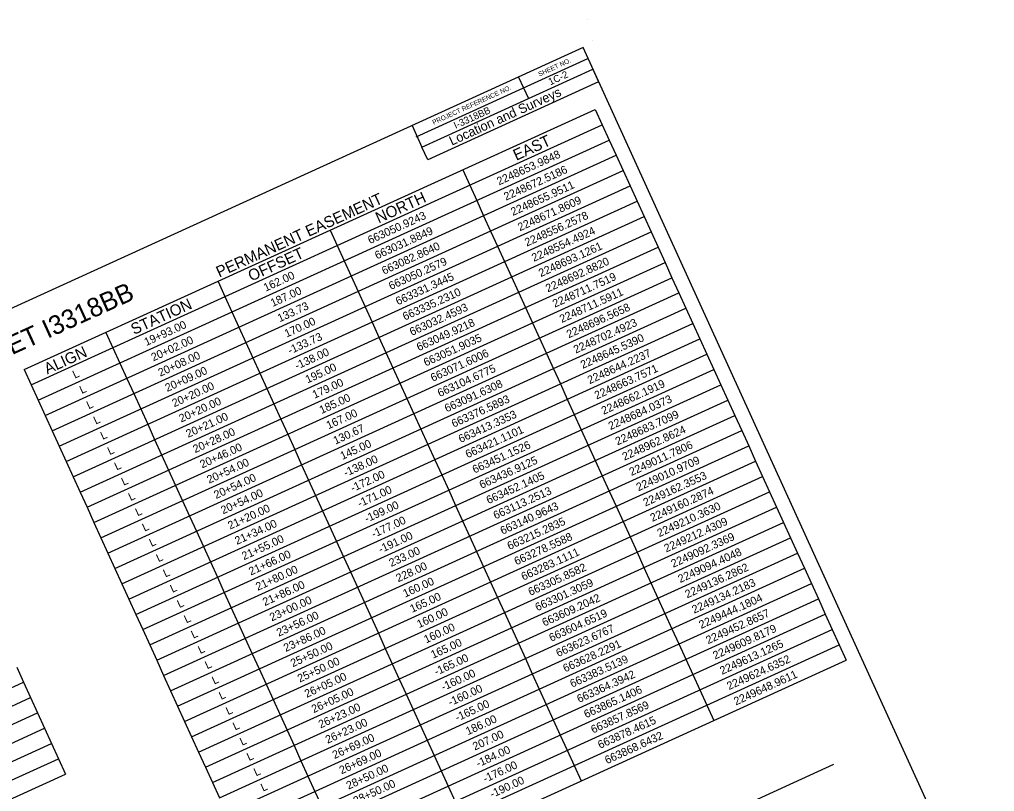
# Model space of a CAD drawing. Extents: x 2253388 to 2258607, y 664121 to 668933.
# Drawn here: x 2255684 to 2258607, y 666618 to 668933 of the extents above; entities that cross this region are included whole.
import ezdxf

# ---------------------------------------------------------------- set-up
doc = ezdxf.new("R2010")
doc.units = 0
for name, color, linetype in [('CTL Sheet Border CELL', 7, 'Continuous'), ('CTL Sheet Notes CELL', 7, 'Continuous'), ('CTL Sheet Table Cell', 7, 'Continuous'), ('CTL Sheet Text', 7, 'Continuous'), ('Default', 7, 'Continuous')]:
    doc.layers.add(name, color=color, linetype=linetype)

msp = doc.modelspace()

# ---------------------------------------------------------------- linework, layer by layer
at = {"layer": 'CTL Sheet Border CELL'}
for p, q in [((2257387.9, 668933), (2257387.9, 668933)), ((2257402.7, 668869.9), (2257402.7, 668869.9)), ((2257402.7, 668869.9), (2257402.7, 668869.9)), ((2256872.9, 668581.3), (2257388.3, 668816.3)), ((2257180.4, 668760.4), (2257209.7, 668696)), ((2256861.1, 668614.8), (2256890.5, 668550.4))]:
    msp.add_line(p, q, dxfattribs=at)
for points in [[(2257373.5, 668848.7), (2253509.6, 667086.2), (2254743.3, 664381.5), (2258607.2, 666143.9)], [(2256890.5, 668550.4), (2257402.9, 668784.2), (2257420.2, 668746.2), (2256907.8, 668512.5)]]:
    msp.add_lwpolyline(points, close=True, dxfattribs=at)
at = {"layer": 'CTL Sheet Notes CELL'}
msp.add_line((2256885.7, 666134.5), (2258125.1, 666699.8), dxfattribs=at)
at = {"layer": 'CTL Sheet Table Cell'}
for p, q in [((2255698.1, 667883.1), (2257410.3, 668663.4)), ((2257410.3, 668663.4), (2257431.2, 668617.5)), ((2255719, 667837.3), (2257431.2, 668617.5)), ((2257431.2, 668617.5), (2257452.1, 668571.6)), ((2255739.9, 667791.4), (2257452.1, 668571.6)), ((2257452.1, 668571.6), (2257473, 668525.8)), ((2255760.8, 667745.6), (2257473, 668525.8)), ((2257473, 668525.8), (2257493.9, 668479.9)), ((2255781.7, 667699.7), (2257493.9, 668479.9)), ((2257012.8, 668482.2), (2257033.7, 668436.4)), ((2257493.9, 668479.9), (2257514.8, 668434.1)), ((2255802.6, 667653.8), (2257514.8, 668434.1)), ((2257033.7, 668436.4), (2257054.6, 668390.5)), ((2257514.8, 668434.1), (2257535.7, 668388.2)), ((2255823.5, 667608), (2257535.7, 668388.2)), ((2257054.6, 668390.5), (2257075.5, 668344.7)), ((2257535.7, 668388.2), (2257556.6, 668342.3)), ((2255844.4, 667562.1), (2257556.6, 668342.3)), ((2257075.5, 668344.7), (2257096.4, 668298.8)), ((2257556.6, 668342.3), (2257577.5, 668296.5)), ((2256615.3, 668301.1), (2256636.2, 668255.3)), ((2255865.3, 667516.2), (2257577.5, 668296.5)), ((2257096.4, 668298.8), (2257117.3, 668252.9)), ((2257577.5, 668296.5), (2257598.4, 668250.6)), ((2255886.2, 667470.4), (2257598.4, 668250.6)), ((2256636.2, 668255.3), (2256657.1, 668209.4)), ((2257117.3, 668252.9), (2257138.2, 668207.1)), ((2257598.4, 668250.6), (2257619.3, 668204.7)), ((2255907.1, 667424.5), (2257619.3, 668204.7)), ((2256657.1, 668209.4), (2256678, 668163.5)), ((2257138.2, 668207.1), (2257159.1, 668161.2)), ((2257619.3, 668204.7), (2257640.2, 668158.9)), ((2255928, 667378.7), (2257640.2, 668158.9)), ((2256678, 668163.5), (2256698.9, 668117.7)), ((2257159.1, 668161.2), (2257180, 668115.3)), ((2257640.2, 668158.9), (2257661.1, 668113)), ((2256279, 668147.9), (2256299.9, 668102)), ((2255948.9, 667332.8), (2257661.1, 668113)), ((2256299.9, 668102), (2256320.8, 668056.1)), ((2256698.9, 668117.7), (2256719.8, 668071.8)), ((2257180, 668115.3), (2257200.9, 668069.5)), ((2257661.1, 668113), (2257682, 668067.2)), ((2255969.8, 667286.9), (2257682, 668067.2)), ((2256719.8, 668071.8), (2256740.7, 668025.9)), ((2257200.9, 668069.5), (2257221.8, 668023.6)), ((2257682, 668067.2), (2257702.9, 668021.3)), ((2256320.8, 668056.1), (2256341.7, 668010.3)), ((2255990.7, 667241.1), (2257702.9, 668021.3)), ((2256341.7, 668010.3), (2256362.6, 667964.4)), ((2256740.7, 668025.9), (2256761.6, 667980.1)), ((2257221.8, 668023.6), (2257242.7, 667977.8)), ((2257702.9, 668021.3), (2257723.8, 667975.4)), ((2255942.7, 667994.6), (2255963.6, 667948.7)), ((2256761.6, 667980.1), (2256782.5, 667934.2)), ((2256011.6, 667195.2), (2257723.8, 667975.4)), ((2256362.6, 667964.4), (2256383.5, 667918.5)), ((2257242.7, 667977.8), (2257263.6, 667931.9)), ((2257723.8, 667975.4), (2257744.7, 667929.6)), ((2255963.6, 667948.7), (2255984.5, 667902.9)), ((2256032.4, 667149.3), (2257744.7, 667929.6)), ((2256782.5, 667934.2), (2256803.4, 667888.4)), ((2257263.6, 667931.9), (2257284.5, 667886)), ((2257744.7, 667929.6), (2257765.6, 667883.7)), ((2255984.5, 667902.9), (2256005.4, 667857)), ((2256383.5, 667918.5), (2256404.4, 667872.7)), ((2255698.1, 667883.1), (2255719, 667837.3)), ((2256053.3, 667103.5), (2257765.6, 667883.7)), ((2256404.4, 667872.7), (2256425.3, 667826.8)), ((2256803.4, 667888.4), (2256824.3, 667842.5)), ((2257284.5, 667886), (2257305.4, 667840.2)), ((2257765.6, 667883.7), (2257786.5, 667837.8)), ((2255719, 667837.3), (2255739.9, 667791.4)), ((2256005.4, 667857), (2256026.3, 667811.2)), ((2256074.2, 667057.6), (2257786.5, 667837.8)), ((2256824.3, 667842.5), (2256845.2, 667796.6)), ((2257305.4, 667840.2), (2257326.3, 667794.3)), ((2257786.5, 667837.8), (2257807.4, 667792)), ((2256026.3, 667811.2), (2256047.2, 667765.3)), ((2256425.3, 667826.8), (2256446.2, 667781)), ((2255739.9, 667791.4), (2255760.8, 667745.6)), ((2256095.1, 667011.7), (2257807.4, 667792)), ((2256446.2, 667781), (2256467.1, 667735.1)), ((2256845.2, 667796.6), (2256866.1, 667750.8)), ((2257326.3, 667794.3), (2257347.2, 667748.4)), ((2257807.4, 667792), (2257828.3, 667746.1)), ((2255760.8, 667745.6), (2255781.7, 667699.7)), ((2256047.2, 667765.3), (2256068.1, 667719.4)), ((2256116, 666965.9), (2257828.3, 667746.1)), ((2256866.1, 667750.8), (2256887, 667704.9)), ((2257347.2, 667748.4), (2257368.1, 667702.6)), ((2257828.3, 667746.1), (2257849.2, 667700.2)), ((2256068.1, 667719.4), (2256089, 667673.6)), ((2256467.1, 667735.1), (2256488, 667689.2)), ((2255781.7, 667699.7), (2255802.6, 667653.8)), ((2256136.9, 666920), (2257849.2, 667700.2)), ((2256488, 667689.2), (2256508.9, 667643.4)), ((2256887, 667704.9), (2256907.9, 667659)), ((2257368.1, 667702.6), (2257389, 667656.7)), ((2257849.2, 667700.2), (2257870.1, 667654.4)), ((2256089, 667673.6), (2256109.9, 667627.7)), ((2256907.9, 667659), (2256928.8, 667613.2)), ((2255802.6, 667653.8), (2255823.5, 667608)), ((2256157.8, 666874.2), (2257870.1, 667654.4)), ((2256508.9, 667643.4), (2256529.8, 667597.5)), ((2257389, 667656.7), (2257409.9, 667610.9)), ((2257870.1, 667654.4), (2257891, 667608.5)), ((2255823.5, 667608), (2255844.4, 667562.1)), ((2256109.9, 667627.7), (2256130.8, 667581.8)), ((2256178.7, 666828.3), (2257891, 667608.5)), ((2256928.8, 667613.2), (2256949.7, 667567.3)), ((2257409.9, 667610.9), (2257430.8, 667565)), ((2257891, 667608.5), (2257911.9, 667562.7)), ((2256130.8, 667581.8), (2256151.7, 667536)), ((2256529.8, 667597.5), (2256550.7, 667551.6)), ((2255844.4, 667562.1), (2255865.3, 667516.2)), ((2256199.6, 666782.4), (2257911.9, 667562.7)), ((2256550.7, 667551.6), (2256571.6, 667505.8)), ((2256949.7, 667567.3), (2256970.6, 667521.5)), ((2257430.8, 667565), (2257451.7, 667519.1)), ((2257911.9, 667562.7), (2257932.8, 667516.8)), ((2255865.3, 667516.2), (2255886.2, 667470.4)), ((2256151.7, 667536), (2256172.6, 667490.1)), ((2256220.5, 666736.6), (2257932.8, 667516.8)), ((2256970.6, 667521.5), (2256991.5, 667475.6)), ((2257451.7, 667519.1), (2257472.6, 667473.3)), ((2257932.8, 667516.8), (2257953.6, 667470.9)), ((2256172.6, 667490.1), (2256193.5, 667444.2)), ((2256571.6, 667505.8), (2256592.5, 667459.9)), ((2255886.2, 667470.4), (2255907.1, 667424.5)), ((2256241.4, 666690.7), (2257953.6, 667470.9)), ((2256592.5, 667459.9), (2256613.4, 667414.1)), ((2256991.5, 667475.6), (2257012.4, 667429.7)), ((2257472.6, 667473.3), (2257493.5, 667427.4)), ((2257953.6, 667470.9), (2257974.5, 667425.1)), ((2255907.1, 667424.5), (2255928, 667378.7)), ((2256193.5, 667444.2), (2256214.4, 667398.4)), ((2256262.3, 666644.8), (2257974.5, 667425.1)), ((2257012.4, 667429.7), (2257033.3, 667383.9)), ((2257493.5, 667427.4), (2257514.4, 667381.5)), ((2257974.5, 667425.1), (2257995.4, 667379.2)), ((2256214.4, 667398.4), (2256235.3, 667352.5)), ((2256613.4, 667414.1), (2256634.3, 667368.2)), ((2255928, 667378.7), (2255948.9, 667332.8)), ((2256283.2, 666599), (2257995.4, 667379.2)), ((2256634.3, 667368.2), (2256655.2, 667322.3)), ((2257033.3, 667383.9), (2257054.2, 667338)), ((2257514.4, 667381.5), (2257535.3, 667335.7)), ((2257995.4, 667379.2), (2258016.3, 667333.3)), ((2256235.3, 667352.5), (2256256.2, 667306.7)), ((2257054.2, 667338), (2257075.1, 667292.1)), ((2255948.9, 667332.8), (2255969.8, 667286.9)), ((2256256.2, 667306.7), (2256277.1, 667260.8)), ((2256304.1, 666553.1), (2258016.3, 667333.3)), ((2256655.2, 667322.3), (2256676.1, 667276.5)), ((2257535.3, 667335.7), (2257556.2, 667289.8)), ((2258016.3, 667333.3), (2258037.2, 667287.5)), ((2255969.8, 667286.9), (2255990.7, 667241.1)), ((2256325, 666507.3), (2258037.2, 667287.5)), ((2257075.1, 667292.1), (2257096, 667246.3)), ((2257556.2, 667289.8), (2257577.1, 667243.9)), ((2258037.2, 667287.5), (2258058.1, 667241.6)), ((2256277.1, 667260.8), (2256297.9, 667214.9)), ((2256676.1, 667276.5), (2256697, 667230.6)), ((2255990.7, 667241.1), (2256011.6, 667195.2)), ((2256345.9, 666461.4), (2258058.1, 667241.6)), ((2256697, 667230.6), (2256717.9, 667184.7)), ((2257096, 667246.3), (2257116.9, 667200.4)), ((2257577.1, 667243.9), (2257598, 667198.1)), ((2258058.1, 667241.6), (2258079, 667195.8)), ((2256011.6, 667195.2), (2256032.4, 667149.3)), ((2256297.9, 667214.9), (2256318.8, 667169.1)), ((2256366.8, 666415.5), (2258079, 667195.8)), ((2257116.9, 667200.4), (2257137.8, 667154.5)), ((2257598, 667198.1), (2257618.9, 667152.2)), ((2258079, 667195.8), (2258099.9, 667149.9)), ((2256318.8, 667169.1), (2256339.7, 667123.2)), ((2256717.9, 667184.7), (2256738.8, 667138.9)), ((2256032.4, 667149.3), (2256053.3, 667103.5)), ((2256387.7, 666369.7), (2258099.9, 667149.9)), ((2256738.8, 667138.9), (2256759.7, 667093)), ((2257137.8, 667154.5), (2257158.7, 667108.7)), ((2257618.9, 667152.2), (2257639.8, 667106.4)), ((2258099.9, 667149.9), (2258120.8, 667104)), ((2256053.3, 667103.5), (2256074.2, 667057.6)), ((2256339.7, 667123.2), (2256360.6, 667077.3)), ((2256408.6, 666323.8), (2258120.8, 667104)), ((2257158.7, 667108.7), (2257179.6, 667062.8)), ((2257639.8, 667106.4), (2257660.7, 667060.5)), ((2258120.8, 667104), (2258141.7, 667058.2)), ((2256360.6, 667077.3), (2256381.5, 667031.5)), ((2256759.7, 667093), (2256780.6, 667047.2)), ((2256074.2, 667057.6), (2256095.1, 667011.7)), ((2256429.5, 666277.9), (2258141.7, 667058.2)), ((2256780.6, 667047.2), (2256801.5, 667001.3)), ((2257179.6, 667062.8), (2257200.5, 667017)), ((2257660.7, 667060.5), (2257681.6, 667014.6)), ((2258141.7, 667058.2), (2258162.6, 667012.3)), ((2256381.5, 667031.5), (2256402.4, 666985.6)), ((2257200.5, 667017), (2257221.4, 666971.1)), ((2257681.6, 667014.6), (2257702.5, 666968.8)), ((2255675.3, 666991.5), (2255696.2, 666945.7)), ((2256095.1, 667011.7), (2256116, 666965.9)), ((2256402.4, 666985.6), (2256423.3, 666939.8)), ((2256450.4, 666232.1), (2258162.6, 667012.3)), ((2256801.5, 667001.3), (2256822.4, 666955.4)), ((2256116, 666965.9), (2256136.9, 666920)), ((2257221.4, 666971.1), (2257242.3, 666925.2)), ((2257702.5, 666968.8), (2257723.4, 666922.9)), ((2253983.9, 666165.4), (2255696.2, 666945.7)), ((2255696.2, 666945.7), (2255717.1, 666899.8)), ((2256423.3, 666939.8), (2256444.2, 666893.9)), ((2256822.4, 666955.4), (2256843.3, 666909.6)), ((2254004.8, 666119.6), (2255717.1, 666899.8)), ((2255717.1, 666899.8), (2255738, 666853.9)), ((2256136.9, 666920), (2256157.8, 666874.2)), ((2256843.3, 666909.6), (2256864.2, 666863.7)), ((2257242.3, 666925.2), (2257263.2, 666879.4)), ((2257723.4, 666922.9), (2257744.3, 666877)), ((2256157.8, 666874.2), (2256178.7, 666828.3)), ((2256444.2, 666893.9), (2256465.1, 666848)), ((2257263.2, 666879.4), (2257284.1, 666833.5)), ((2257744.3, 666877), (2257765.2, 666831.2)), ((2254025.7, 666073.7), (2255738, 666853.9)), ((2255738, 666853.9), (2255758.9, 666808.1)), ((2256465.1, 666848), (2256486, 666802.2)), ((2256864.2, 666863.7), (2256885.1, 666817.8)), ((2256178.7, 666828.3), (2256199.6, 666782.4)), ((2256885.1, 666817.8), (2256906, 666772)), ((2257284.1, 666833.5), (2257305, 666787.6)), ((2254046.6, 666027.8), (2255758.9, 666808.1)), ((2255758.9, 666808.1), (2255779.8, 666762.2)), ((2256199.6, 666782.4), (2256220.5, 666736.6)), ((2256486, 666802.2), (2256506.9, 666756.3)), ((2257305, 666787.6), (2257325.9, 666741.8)), ((2254067.5, 665982), (2255779.8, 666762.2)), ((2255779.8, 666762.2), (2255800.6, 666716.3)), ((2256506.9, 666756.3), (2256527.8, 666710.4)), ((2256906, 666772), (2256926.9, 666726.1)), ((2256220.5, 666736.6), (2256241.4, 666690.7)), ((2256926.9, 666726.1), (2256947.8, 666680.3)), ((2257325.9, 666741.8), (2257346.8, 666695.9)), ((2254088.4, 665936.1), (2255800.6, 666716.3)), ((2255800.6, 666716.3), (2255821.5, 666670.5)), ((2256527.8, 666710.4), (2256548.7, 666664.6)), ((2257346.8, 666695.9), (2257367.7, 666650.1)), ((2254109.3, 665890.3), (2255821.5, 666670.5)), ((2256241.4, 666690.7), (2256262.3, 666644.8)), ((2256548.7, 666664.6), (2256569.6, 666618.7)), ((2256947.8, 666680.3), (2256968.7, 666634.4)), ((2256262.3, 666644.8), (2256283.2, 666599)), ((2256968.7, 666634.4), (2256989.6, 666588.5)), ((2256569.6, 666618.7), (2256590.5, 666572.9))]:
    msp.add_line(p, q, dxfattribs=at)

# ---------------------------------------------------------------- texts
at = {"layer": 'CTL Sheet Border CELL'}
for s, height, p in [('SHEET NO.', 14.16, (2257243, 668761.7)), ('PROJECT REFERENCE NO.', 14.157, (2256925.6, 668617.3)), ('Location and Surveys', 28.313, (2256980, 668554.4)), ('SURVEY CONTROL SHEET I3318BB', 56.625, (2254860.8, 667561.4))]:
    msp.add_text(s, height=height, rotation=24.5191, dxfattribs=at).set_placement(p)
at = {"layer": 'CTL Sheet Notes CELL'}
for s, p in [('EAST', (2257173.3, 668509.2)), ('PERMANENT EASEMENT', (2256282.7, 668158.8)), ('NORTH', (2256760.7, 668321.2)), ('OFFSET', (2256378.6, 668147.1)), ('STATION', (2256027.1, 667986.9)), ('ALIGN', (2255767, 667868.4))]:
    msp.add_text(s, height=33.6, rotation=24.4979, dxfattribs=at).set_placement(p)
at = {"layer": 'CTL Sheet Text'}
for s, p in [('2248653.9848', (2257121.5, 668435.5)), ('2248672.5186', (2257142.4, 668389.6)), ('2248655.9511', (2257163.3, 668343.8)), ('2248671.8609', (2257184.2, 668297.9)), ('663050.9243', (2256734.8, 668259.3)), ('2248556.2578', (2257205.1, 668252)), ('663031.8849', (2256755.7, 668213.4)), ('2248554.4924', (2257226, 668206.2)), ('663082.8640', (2256776.6, 668167.6)), ('2248693.1261', (2257246.9, 668160.3)), ('663050.2579', (2256797.5, 668121.7)), ('2248692.8820', (2257267.8, 668114.5)), ('162.00', (2256422.1, 668116.8)), ('663331.3445', (2256818.4, 668075.9)), ('2248711.7519', (2257288.7, 668068.6)), ('187.00', (2256443, 668070.9)), ('663335.2310', (2256839.3, 668030)), ('2248711.5911', (2257309.6, 668022.7)), ('133.73', (2256463.9, 668025.1)), ('663032.4593', (2256860.2, 667984.1)), ('2248696.5658', (2257330.5, 667976.9)), ('170.00', (2256484.8, 667979.2)), ('19+93.00', (2256064.1, 667953.7)), ('663049.9218', (2256881.1, 667938.3)), ('2248702.4923', (2257351.4, 667931)), ('20+02.00', (2256085, 667907.8)), ('-133.73', (2256494.9, 667928.4)), ('663051.9035', (2256902, 667892.4)), ('2248645.5390', (2257372.3, 667885.1)), ('20+08.00', (2256105.9, 667861.9)), ('-138.00', (2256515.8, 667882.6)), ('663071.6006', (2256922.9, 667846.5)), ('2248644.2237', (2257393.2, 667839.3)), ('20+09.00', (2256126.8, 667816.1)), ('195.00', (2256547.5, 667841.6)), ('663104.6775', (2256943.8, 667800.7)), ('2248663.7571', (2257414.1, 667793.4)), ('L', (2255849.5, 667855.9)), ('L', (2255870.4, 667810)), ('20+20.00', (2256147.7, 667770.2)), ('179.00', (2256568.4, 667795.8)), ('663091.6308', (2256964.7, 667754.8)), ('2248662.1919', (2257435, 667747.6)), ('185.00', (2256589.3, 667749.9)), ('663376.5893', (2256985.6, 667709)), ('2248684.0373', (2257455.9, 667701.7)), ('L', (2255891.3, 667764.1)), ('20+20.00', (2256168.6, 667724.4)), ('20+21.00', (2256189.5, 667678.5)), ('167.00', (2256610.2, 667704)), ('663413.3353', (2257006.5, 667663.1)), ('2248683.7099', (2257476.8, 667655.8)), ('L', (2255912.2, 667718.3)), ('130.67', (2256631.1, 667658.2)), ('L', (2255933.1, 667672.4)), ('20+28.00', (2256210.4, 667632.6)), ('663421.1101', (2257027.4, 667617.2)), ('2248962.8624', (2257497.6, 667610)), ('20+46.00', (2256231.3, 667586.8)), ('145.00', (2256652, 667612.3)), ('663451.1526', (2257048.3, 667571.4)), ('2249011.7806', (2257518.5, 667564.1)), ('L', (2255954, 667626.6)), ('L', (2255974.9, 667580.7)), ('20+54.00', (2256252.2, 667540.9)), ('-138.00', (2256662, 667561.5)), ('663436.9125', (2257069.2, 667525.5)), ('2249010.9709', (2257539.4, 667518.2)), ('20+54.00', (2256273.1, 667495)), ('-172.00', (2256682.9, 667515.6)), ('663452.1405', (2257090.1, 667479.6)), ('2249162.3553', (2257560.3, 667472.4)), ('L', (2255995.8, 667534.8)), ('L', (2256016.7, 667489)), ('20+54.00', (2256294, 667449.2)), ('-171.00', (2256703.8, 667469.8)), ('663113.2513', (2257111, 667433.8)), ('2249160.2874', (2257581.2, 667426.5)), ('-199.00', (2256724.7, 667423.9)), ('663140.9643', (2257131.9, 667387.9)), ('2249210.3630', (2257602.1, 667380.7)), ('L', (2256037.6, 667443.1)), ('21+20.00', (2256314.9, 667403.3)), ('21+34.00', (2256335.8, 667357.5)), ('-177.00', (2256745.6, 667378.1)), ('663215.2835', (2257152.8, 667342.1)), ('2249212.4309', (2257623, 667334.8)), ('L', (2256058.5, 667397.2)), ('-191.00', (2256766.5, 667332.2)), ('L', (2256079.4, 667351.4)), ('21+55.00', (2256356.7, 667311.6)), ('663278.5588', (2257173.7, 667296.2)), ('2249092.3369', (2257643.9, 667288.9)), ('21+66.00', (2256377.6, 667265.7)), ('233.00', (2256798.3, 667291.3)), ('663283.1111', (2257194.6, 667250.3)), ('2249094.4048', (2257664.8, 667243.1)), ('L', (2256100.3, 667305.5)), ('L', (2256121.2, 667259.7)), ('21+80.00', (2256398.5, 667219.9)), ('228.00', (2256819.2, 667245.4)), ('663305.8582', (2257215.5, 667204.5)), ('2249136.2862', (2257685.7, 667197.2)), ('21+86.00', (2256419.4, 667174)), ('160.00', (2256840.1, 667199.5)), ('663301.3059', (2257236.4, 667158.6)), ('2249134.2183', (2257706.6, 667151.3)), ('L', (2256142.1, 667213.8)), ('L', (2256163, 667167.9)), ('23+00.00', (2256440.3, 667128.1)), ('165.00', (2256861, 667153.7)), ('663609.2042', (2257257.3, 667112.7)), ('2249444.1804', (2257727.5, 667105.5)), ('160.00', (2256881.9, 667107.8)), ('663604.6519', (2257278.2, 667066.9)), ('2249452.8657', (2257748.4, 667059.6)), ('L', (2256183.9, 667122.1)), ('23+56.00', (2256461.2, 667082.3)), ('23+86.00', (2256482.1, 667036.4)), ('160.00', (2256902.8, 667062)), ('663623.6767', (2257299.1, 667021)), ('2249609.8179', (2257769.3, 667013.7)), ('L', (2256204.8, 667076.2)), ('165.00', (2256923.7, 667016.1)), ('2249613.1265', (2257790.2, 666967.9)), ('L', (2256225.6, 667030.3)), ('25+50.00', (2256503, 666990.6)), ('663628.2291', (2257320, 666975.2)), ('25+50.00', (2256523.9, 666944.7)), ('-165.00', (2256933.7, 666965.3)), ('663383.5139', (2257340.9, 666929.3)), ('2249624.6352', (2257811.1, 666922)), ('L', (2256246.5, 666984.5)), ('L', (2256267.4, 666938.6)), ('26+05.00', (2256544.8, 666898.8)), ('-160.00', (2256954.6, 666919.4)), ('663364.3942', (2257361.8, 666883.4)), ('2249648.9611', (2257832, 666876.2)), ('26+05.00', (2256565.7, 666853)), ('-160.00', (2256975.5, 666873.6)), ('663865.1406', (2257382.7, 666837.6)), ('L', (2256288.3, 666892.7)), ('L', (2256309.2, 666846.9)), ('26+23.00', (2256586.6, 666807.1)), ('-165.00', (2256996.4, 666827.7)), ('663857.8569', (2257403.6, 666791.7)), ('186.00', (2257028.2, 666786.8)), ('663878.4615', (2257424.5, 666745.8)), ('L', (2256330.1, 666801)), ('26+23.00', (2256607.5, 666761.2)), ('26+69.00', (2256628.4, 666715.4)), ('207.00', (2257049.1, 666740.9)), ('663868.6432', (2257445.4, 666700)), ('L', (2256351, 666755.2)), ('-184.00', (2257059.1, 666690.1)), ('L', (2256371.9, 666709.3)), ('26+69.00', (2256649.3, 666669.5)), ('28+50.00', (2256670.2, 666623.6)), ('-176.00', (2257080, 666644.3)), ('L', (2256392.8, 666663.4)), ('-190.00', (2257100.9, 666598.4)), ('L', (2256413.7, 666617.6)), ('28+50.00', (2256691.1, 666577.8))]:
    msp.add_text(s, height=24, rotation=24.4979, dxfattribs=at).set_placement(p)
at = {"layer": 'Default'}
for s, p in [('1C-2', (2257275.4, 668735.5)), ('I-3318BB', (2256991.4, 668604.8))]:
    msp.add_text(s, height=21.09, rotation=24.5191, dxfattribs=at).set_placement(p)

doc.saveas('drawing.dxf')
